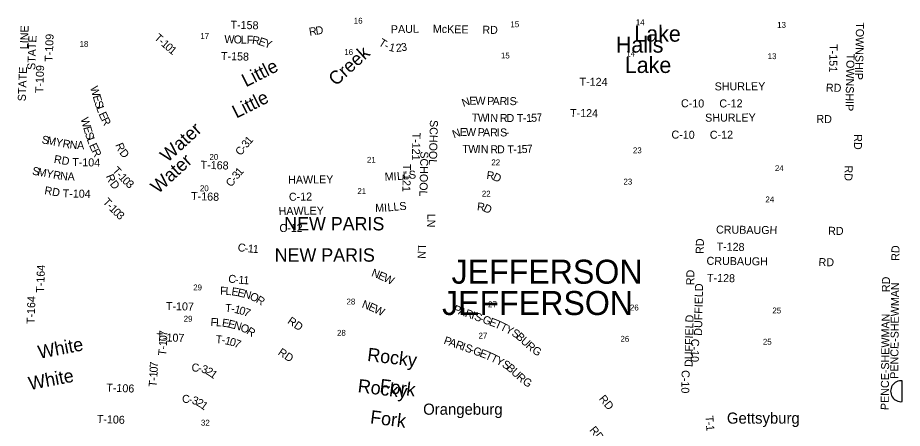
# Model space of a CAD drawing. Extents: x -21.9 to 47.3, y 14.1 to 48.7.
# Drawn here: x -21.92 to -15.64, y 44.7 to 47.62 of the extents above; entities that cross this region are included whole.
import ezdxf

# ---------------------------------------------------------------- set-up
doc = ezdxf.new("R2010")
doc.units = 0
for name, color, linetype in [('GM_X_Corporation_Text', 7, 'Continuous'), ('GM_X_County_Road_Text', 7, 'Continuous'), ('GM_X_Major_River_Text', 7, 'Continuous'), ('GM_X_Minor_Lake_Text', 7, 'Continuous'), ('GM_X_Minor_River_Text', 7, 'Continuous'), ('GM_X_Section_Text', 7, 'Continuous'), ('GM_X_Township_Road_Text', 7, 'Continuous'), ('GM_X_Township_Text', 7, 'Continuous'), ('GM_X_Unincorporated_Text', 7, 'Continuous')]:
    doc.layers.add(name, color=color, linetype=linetype)

msp = doc.modelspace()

# ---------------------------------------------------------------- linework, layer by layer
at = {"layer": 'GM_X_Major_River_Text'}
msp.add_line((-15.6413, 44.8898), (-15.6413, 45.0376), dxfattribs=at)
msp.add_arc((-15.6499, 44.9637), 0.0744, 83.38525, 276.61475, dxfattribs=at)

# ---------------------------------------------------------------- texts
at = {"layer": 'GM_X_Corporation_Text'}
for p in [(-20.0268, 46.1054), (-20.0942, 45.8832)]:
    msp.add_text('NEW PARIS', height=0.0947, rotation=0.00001, dxfattribs=at).set_placement(p)
at = {"layer": 'GM_X_County_Road_Text'}
for s, height, rotation, p in [('SHURLEY', 0.05682, 0.29863, (-16.9725, 47.0991)), ('RD', 0.05682, 359.01278, (-16.1837, 47.0907)), ('C-10', 0.05682, 359.31423, (-17.2119, 46.9797)), ('C-12', 0.05682, 0.3429, (-16.9393, 46.978)), ('SHURLEY', 0.05682, 0.29863, (-17.0399, 46.8769)), ('RD', 0.05682, 359.01278, (-16.2511, 46.8685)), ('1', 0.0568, 48.42145, (-20.27, 46.7132)), ('C-10', 0.05682, 359.31423, (-17.2793, 46.7575)), ('C-12', 0.05682, 0.3429, (-17.0067, 46.7558)), ('C', 0.0568, 51.88765, (-20.3347, 46.6316)), ('3', 0.0568, 50.98767, (-20.2916, 46.6865)), ('-', 0.0568, 51.69294, (-20.3059, 46.6683)), ('3', 0.0568, 50.98767, (-20.359, 46.4643)), ('1', 0.0568, 48.42145, (-20.3374, 46.491)), ('M', 0.0568, 1.38832, (-19.3133, 46.4591)), ('I', 0.0568, 3.49277, (-19.2494, 46.4606)), ('L', 0.0568, 5.02783, (-19.2244, 46.4622)), ('L', 0.0568, 5.39561, (-19.1817, 46.466)), ('S', 0.0568, 5.40075, (-19.1394, 46.47)), ('R', 0.0568, 353.33041, (-18.5934, 46.4706)), ('D', 0.0568, 334.82796, (-18.5517, 46.4665)), ('C', 0.0568, 51.88765, (-20.4021, 46.4094)), ('-', 0.0568, 51.69294, (-20.3733, 46.4461)), ('HAWLEY', 0.05682, 0.63509, (-19.9985, 46.4366)), ('C-12', 0.05682, 0.68708, (-19.9929, 46.3155)), ('HAWLEY', 0.05682, 0.63509, (-20.0659, 46.2144)), ('M', 0.0568, 1.38832, (-19.3807, 46.2369)), ('I', 0.0568, 3.49277, (-19.3168, 46.2385)), ('L', 0.0568, 5.02783, (-19.2918, 46.24)), ('L', 0.0568, 5.39561, (-19.2491, 46.2438)), ('S', 0.0568, 5.40075, (-19.2068, 46.2478)), ('R', 0.0568, 353.33041, (-18.6608, 46.2484)), ('D', 0.0568, 334.82796, (-18.6191, 46.2443)), ('C-12', 0.05682, 0.68708, (-20.0603, 46.0933)), ('C', 0.0568, 352.13029, (-20.3591, 45.9591)), ('1', 0.0568, 355.20707, (-20.2863, 45.9501)), ('RD', 0.05682, 89.01231, (-17.0506, 45.9379)), ('-', 0.0568, 354.33802, (-20.3105, 45.9525)), ('1', 0.0568, 355.53507, (-20.2511, 45.9471)), ('N', 0.0568, 339.45824, (-19.4123, 45.7825)), ('RD', 0.05682, 89.01231, (-17.118, 45.7157)), ('C', 0.0568, 352.13029, (-20.4265, 45.7369)), ('-', 0.0568, 354.33802, (-20.3779, 45.7303)), ('1', 0.0568, 355.20707, (-20.3537, 45.7279)), ('1', 0.0568, 355.53507, (-20.3185, 45.7249)), ('E', 0.0568, 335.24664, (-19.3665, 45.7653)), ('W', 0.0568, 334.78636, (-19.328, 45.7476)), ('DUFFIELD', 0.05682, 88.8627, (-17.0623, 45.3571)), ('N', 0.0568, 339.45824, (-19.4797, 45.5603)), ('E', 0.0568, 335.24664, (-19.4339, 45.5432)), ('W', 0.0568, 334.78636, (-19.3954, 45.5254)), ('P', 0.0568, 340.45593, (-18.8317, 45.5242)), ('A', 0.0568, 340.45494, (-18.7956, 45.5114)), ('R', 0.0568, 340.45674, (-18.7485, 45.4947)), ('I', 0.0568, 340.45204, (-18.7045, 45.4791)), ('S', 0.0568, 340.45729, (-18.6825, 45.4712)), ('DUFFIELD', 0.05682, 88.8627, (-17.1296, 45.135)), ('-', 0.0568, 340.45204, (-18.6464, 45.4584)), ('G', 0.0568, 340.41246, (-18.6244, 45.4506)), ('E', 0.0568, 339.43618, (-18.5775, 45.4339)), ('T', 0.0568, 335.95223, (-18.5386, 45.4194)), ('T', 0.0568, 333.94644, (-18.5003, 45.4023)), ('Y', 0.0568, 333.69541, (-18.4621, 45.3836)), ('S', 0.0568, 329.73826, (-18.4182, 45.362)), ('B', 0.0568, 318.00507, (-18.3876, 45.3445)), ('P', 0.0568, 340.45593, (-18.8991, 45.302)), ('A', 0.0568, 340.45494, (-18.863, 45.2892)), ('R', 0.0568, 340.45674, (-18.8159, 45.2725)), ('U', 0.0568, 317.05527, (-18.3531, 45.3134)), ('R', 0.0568, 317.31826, (-18.3163, 45.2791)), ('C-10', 0.05682, 268.97107, (-17.1394, 45.336)), ('I', 0.0568, 340.45204, (-18.7719, 45.2569)), ('S', 0.0568, 340.45729, (-18.7499, 45.2491)), ('-', 0.0568, 340.45204, (-18.7138, 45.2362)), ('G', 0.0568, 340.41246, (-18.6918, 45.2284)), ('E', 0.0568, 339.43618, (-18.6449, 45.2118)), ('G', 0.0568, 328.02168, (-18.2728, 45.2405)), ('T', 0.0568, 335.95223, (-18.606, 45.1972)), ('T', 0.0568, 333.94644, (-18.5677, 45.1801)), ('Y', 0.0568, 333.69541, (-18.5295, 45.1614)), ('C', 0.0568, 357.95416, (-20.6846, 45.1039)), ('-', 0.0568, 352.33407, (-20.6395, 45.1023)), ('3', 0.0568, 341.09389, (-20.6192, 45.0999)), ('2', 0.0568, 329.85372, (-20.5888, 45.0898)), ('S', 0.0568, 329.73826, (-18.4856, 45.1398)), ('B', 0.0568, 318.00507, (-18.455, 45.1223)), ('U', 0.0568, 317.05527, (-18.4205, 45.0912)), ('1', 0.0568, 324.23363, (-20.5597, 45.073)), ('R', 0.0568, 317.31826, (-18.3837, 45.057)), ('C-10', 0.05682, 268.97107, (-17.2068, 45.1138)), ('G', 0.0568, 328.02168, (-18.3402, 45.0183)), ('C', 0.0568, 357.95416, (-20.752, 44.8817)), ('RD', 0.05682, 309.74193, (-17.7969, 44.9085)), ('-', 0.0568, 352.33407, (-20.7069, 44.8801)), ('3', 0.0568, 341.09389, (-20.6866, 44.8777)), ('2', 0.0568, 329.85372, (-20.6562, 44.8676)), ('1', 0.0568, 324.23363, (-20.6271, 44.8508)), ('RD', 0.05682, 309.74193, (-17.8643, 44.6863))]:
    msp.add_text(s, height=height, rotation=rotation, dxfattribs=at).set_placement(p)
at = {"layer": 'GM_X_Minor_Lake_Text'}
for s, rotation, p in [('Lake', 0.00663, (-17.5424, 47.4451)), ('Halls', 0.00679, (-17.6738, 47.3673)), ('Lake', 0.00663, (-17.6098, 47.2229))]:
    msp.add_text(s, height=0.11363, rotation=rotation, dxfattribs=at).set_placement(p)
at = {"layer": 'GM_X_Minor_River_Text'}
for s, height, rotation, p in [('Creek', 0.09467, 42.35798, (-19.6597, 47.1263)), ('Little', 0.09468, 26.87284, (-20.2983, 47.1205)), ('Little', 0.09468, 26.87284, (-20.3657, 46.8983)), ('Water', 0.09466, 42.35347, (-20.854, 46.5836)), ('Water', 0.09466, 42.35347, (-20.9214, 46.3614)), ('White', 0.09469, 10.82648, (-21.764, 45.1933)), ('Rocky', 0.09469, 352.89105, (-19.4408, 45.1793)), ('White', 0.09469, 10.82648, (-21.8314, 44.9711)), ('Rocky', 0.09469, 352.89105, (-19.5082, 44.9571)), ('Fork', 0.09469, 352.89084, (-19.3528, 44.9581)), ('Fork', 0.09469, 352.89084, (-19.4202, 44.7359))]:
    msp.add_text(s, height=height, rotation=rotation, dxfattribs=at).set_placement(p)
at = {"layer": 'GM_X_Section_Text'}
for s, p in [('16', (-19.5328, 47.573)), ('15', (-18.4216, 47.5481)), ('14', (-17.532, 47.5621)), ('13', (-16.5291, 47.5434)), ('18', (-21.4785, 47.4079)), ('17', (-20.6215, 47.4651)), ('16', (-19.6002, 47.3508)), ('15', (-18.489, 47.3259)), ('14', (-17.5994, 47.3399)), ('13', (-16.5965, 47.3212)), ('23', (-17.5524, 46.653)), ('20', (-20.557, 46.6059)), ('21', (-19.4399, 46.5854)), ('22', (-18.557, 46.5671)), ('24', (-16.5453, 46.5262)), ('23', (-17.6198, 46.4308)), ('20', (-20.6244, 46.3837)), ('21', (-19.5073, 46.3632)), ('22', (-18.6244, 46.3449)), ('24', (-16.6127, 46.3041)), ('29', (-20.6724, 45.6793)), ('28', (-19.5845, 45.5793)), ('27', (-18.5803, 45.5593)), ('26', (-17.5737, 45.5368)), ('25', (-16.5632, 45.5159)), ('29', (-20.7398, 45.4571)), ('28', (-19.6519, 45.3571)), ('27', (-18.6477, 45.3371)), ('26', (-17.641, 45.3146)), ('25', (-16.6306, 45.2937)), ('32', (-20.617, 44.7193))]:
    msp.add_text(s, height=0.04186, rotation=0.00001, dxfattribs=at).set_placement(p)
at = {"layer": 'GM_X_Township_Road_Text'}
for s, height, rotation, p in [('T-158', 0.05682, 358.59567, (-20.4081, 47.5373)), ('TOWNSHIP', 0.05682, 268.80363, (-15.9692, 47.5837)), ('LINE', 0.05682, 87.9954, (-21.8454, 47.391)), ('R', 0.0568, 9.17599, (-19.8459, 47.4866)), ('D', 0.0568, 8.20602, (-19.8, 47.494)), ('PAUL', 0.05682, 1.32402, (-19.2693, 47.5044)), ('McKEE', 0.05682, 358.78533, (-18.9726, 47.5085)), ('RD', 0.05682, 359.02012, (-18.6213, 47.5019)), ('STATE', 0.05682, 87.78889, (-21.7931, 47.2434)), ('T-109', 0.05682, 87.7543, (-21.6697, 47.3012)), ('T', 0.0568, 318.26325, (-20.9533, 47.4662)), ('-', 0.0568, 318.28073, (-20.9215, 47.4379)), ('1', 0.0568, 318.34053, (-20.9041, 47.4223)), ('W', 0.0568, 358.48093, (-20.4517, 47.4352)), ('O', 0.0568, 358.48079, (-20.3859, 47.4334)), ('L', 0.0568, 358.48423, (-20.3359, 47.4321)), ('F', 0.0568, 358.3843, (-20.2934, 47.431)), ('R', 0.0568, 352.50053, (-20.2567, 47.43)), ('E', 0.0568, 341.17068, (-20.2133, 47.4246)), ('Y', 0.0568, 340.99138, (-20.1731, 47.4109)), ('T', 0.0568, 328.11455, (-19.3613, 47.4234)), ('0', 0.0568, 318.59425, (-20.8777, 47.3989)), ('1', 0.0568, 320.1977, (-20.8502, 47.3746)), ('-', 0.0568, 330.34481, (-19.3231, 47.3998)), ('1', 0.0568, 345.41201, (-19.2878, 47.3821)), ('2', 0.0568, 6.3204, (-19.2315, 47.3717)), ('3', 0.0568, 10.08346, (-19.1927, 47.3761)), ('T-151', 0.05682, 268.87678, (-16.1567, 47.4281)), ('T-158', 0.05682, 358.59567, (-20.4755, 47.3151)), ('TOWNSHIP', 0.05682, 268.80363, (-16.0366, 47.3615)), ('STATE', 0.05682, 87.78889, (-21.8605, 47.0212)), ('T-109', 0.05682, 87.7543, (-21.7371, 47.079)), ('W', 0.0568, 286.14534, (-21.4043, 47.1205)), ('T-124', 0.05682, 359.71822, (-17.9312, 47.1323)), ('E', 0.0568, 286.28182, (-21.3859, 47.0571)), ('S', 0.0568, 287.55111, (-21.3736, 47.015)), ('N', 0.0568, 19.33248, (-18.755, 46.981)), ('E', 0.0568, 1.79168, (-18.7123, 46.9967)), ('W', 0.0568, 359.31385, (-18.6705, 46.998)), ('P', 0.0568, 359.04386, (-18.5872, 46.9969)), ('A', 0.0568, 359.04555, (-18.5489, 46.9963)), ('R', 0.0568, 359.09318, (-18.4988, 46.9954)), ('I', 0.0568, 359.59008, (-18.4516, 46.9947)), ('S', 0.0568, 0.40975, (-18.4274, 46.9945)), ('-', 0.0568, 1.18896, (-18.3882, 46.9948)), ('L', 0.0568, 289.94001, (-21.3612, 46.976)), ('E', 0.0568, 294.21387, (-21.345, 46.9318)), ('T-124', 0.05682, 359.71822, (-17.9986, 46.9101)), ('W', 0.0568, 286.14534, (-21.4717, 46.8983)), ('R', 0.0568, 295.97741, (-21.3267, 46.8913)), ('SCHOOL', 0.05682, 268.62372, (-18.9925, 46.8895)), ('T', 0.0568, 359.14285, (-18.6964, 46.8782)), ('W', 0.0568, 359.1423, (-18.6539, 46.8776)), ('I', 0.0568, 359.14869, (-18.588, 46.8766)), ('N', 0.0568, 359.14875, (-18.5647, 46.8762)), ('R', 0.0568, 359.28834, (-18.4971, 46.8752)), ('D', 0.0568, 0.01456, (-18.4496, 46.8747)), ('T', 0.0568, 1.08432, (-18.3755, 46.8739)), ('-', 0.0568, 1.12693, (-18.333, 46.8747)), ('1', 0.0568, 1.27135, (-18.3095, 46.8752)), ('5', 0.0568, 1.79762, (-18.274, 46.876)), ('7', 0.0568, 5.18162, (-18.2353, 46.8773)), ('E', 0.0568, 286.28182, (-21.4533, 46.8349)), ('N', 0.0568, 19.33248, (-18.8224, 46.7588)), ('E', 0.0568, 1.79168, (-18.7797, 46.7745)), ('W', 0.0568, 359.31385, (-18.7378, 46.7758)), ('P', 0.0568, 359.04386, (-18.6546, 46.7747)), ('A', 0.0568, 359.04555, (-18.6163, 46.7741)), ('R', 0.0568, 359.09318, (-18.5662, 46.7733)), ('I', 0.0568, 359.59008, (-18.519, 46.7725)), ('S', 0.0568, 0.40975, (-18.4948, 46.7723)), ('S', 0.0568, 349.34784, (-21.7501, 46.7244)), ('M', 0.0568, 349.34924, (-21.7124, 46.7173)), ('Y', 0.0568, 349.34926, (-21.6518, 46.7059)), ('S', 0.0568, 287.55111, (-21.441, 46.7928)), ('L', 0.0568, 289.94001, (-21.4286, 46.7538)), ('T-121', 0.05682, 268.59595, (-19.116, 46.8)), ('-', 0.0568, 1.18896, (-18.4556, 46.7726)), ('RD', 0.05682, 269.50588, (-15.9834, 46.7882)), ('R', 0.0568, 349.95064, (-21.6021, 46.6965)), ('N', 0.0568, 354.61352, (-21.5511, 46.6877)), ('A', 0.0568, 358.73308, (-21.4969, 46.6828)), ('E', 0.0568, 294.21387, (-21.4124, 46.7096)), ('R', 0.0568, 292.28528, (-21.2257, 46.7131)), ('T', 0.0568, 359.14285, (-18.7637, 46.656)), ('W', 0.0568, 359.1423, (-18.7213, 46.6554)), ('I', 0.0568, 359.14869, (-18.6554, 46.6544)), ('N', 0.0568, 359.14875, (-18.6321, 46.6541)), ('R', 0.0568, 359.28834, (-18.5645, 46.6531)), ('D', 0.0568, 0.01456, (-18.517, 46.6525)), ('T', 0.0568, 1.08432, (-18.4429, 46.6517)), ('1', 0.0568, 1.27135, (-18.3769, 46.653)), ('5', 0.0568, 1.79762, (-18.3413, 46.6538)), ('7', 0.0568, 5.18162, (-18.3027, 46.6551)), ('RD', 0.05682, 350.04916, (-21.6634, 46.5855)), ('R', 0.0568, 295.97741, (-21.3941, 46.6691)), ('D', 0.0568, 308.63938, (-21.1992, 46.655)), ('SCHOOL', 0.05682, 268.62372, (-19.0599, 46.6673)), ('-', 0.0568, 1.12693, (-18.4004, 46.6526)), ('T-104', 0.05682, 358.88104, (-21.5312, 46.5623)), ('T-168', 0.05682, 358.30687, (-20.6203, 46.5431)), ('T-121', 0.05682, 268.59595, (-19.1834, 46.5778)), ('S', 0.0568, 349.34784, (-21.8175, 46.5022)), ('M', 0.0568, 349.34924, (-21.7798, 46.4951)), ('Y', 0.0568, 349.34926, (-21.7192, 46.4837)), ('R', 0.0568, 349.95064, (-21.6694, 46.4743)), ('N', 0.0568, 354.61352, (-21.6185, 46.4655)), ('A', 0.0568, 358.73308, (-21.5643, 46.4606)), ('R', 0.0568, 292.28528, (-21.2931, 46.4909)), ('T', 0.0568, 313.0373, (-21.2502, 46.5261)), ('-', 0.0568, 313.12882, (-21.2212, 46.4949)), ('RD', 0.05682, 269.50588, (-16.0508, 46.566)), ('D', 0.0568, 308.63938, (-21.2666, 46.4328)), ('1', 0.0568, 313.48218, (-21.2049, 46.4776)), ('0', 0.0568, 314.85589, (-21.1798, 46.4511)), ('3', 0.0568, 319.26324, (-21.1543, 46.4256)), ('RD', 0.05682, 350.04916, (-21.7308, 46.3633)), ('T-104', 0.05682, 358.88104, (-21.5986, 46.3401)), ('T', 0.0568, 313.0373, (-21.3176, 46.3039)), ('T-168', 0.05682, 358.30687, (-20.6877, 46.3209)), ('-', 0.0568, 313.12882, (-21.2885, 46.2727)), ('1', 0.0568, 313.48218, (-21.2723, 46.2554)), ('0', 0.0568, 314.85589, (-21.2472, 46.229)), ('3', 0.0568, 319.26324, (-21.2217, 46.2034)), ('LN', 0.05682, 268.4517, (-19.0101, 46.2244)), ('CRUBAUGH', 0.05682, 359.38823, (-16.963, 46.0832)), ('RD', 0.05682, 359.50635, (-16.168, 46.0741)), ('T-128', 0.05682, 359.15794, (-16.9597, 45.9623)), ('LN', 0.05682, 268.4517, (-19.0775, 46.0022)), ('RD', 0.05682, 89.50633, (-15.6622, 45.8894)), ('CRUBAUGH', 0.05682, 359.38823, (-17.0304, 45.8611)), ('RD', 0.05682, 359.50635, (-16.2354, 45.8519)), ('T-164', 0.05682, 88.03472, (-21.7305, 45.6617)), ('T-128', 0.05682, 359.15794, (-17.0271, 45.7401)), ('RD', 0.05682, 89.50633, (-15.7296, 45.6672)), ('F', 0.0568, 357.68067, (-20.4825, 45.649)), ('L', 0.0568, 356.96007, (-20.4444, 45.6475)), ('E', 0.0568, 352.17589, (-20.4032, 45.6454)), ('E', 0.0568, 346.26194, (-20.3626, 45.6399)), ('PENCE-SHEWMAN', 0.056818, 89.44451, (-15.6706, 45.0519)), ('T-164', 0.05682, 88.03472, (-21.7979, 45.4395)), ('N', 0.0568, 344.29691, (-20.3218, 45.6299)), ('O', 0.0568, 336.52333, (-20.2756, 45.6171)), ('R', 0.0568, 327.66401, (-20.2318, 45.5982)), ('T-107', 0.05682, 358.60252, (-20.8665, 45.5406)), ('T', 0.0568, 355.85648, (-20.4472, 45.5274)), ('1', 0.0568, 346.00841, (-20.3843, 45.521)), ('0', 0.0568, 344.52854, (-20.3507, 45.5127)), ('-', 0.0568, 350.85161, (-20.4061, 45.5245)), ('7', 0.0568, 338.38897, (-20.3185, 45.5038)), ('PENCE-SHEWMAN', 0.056818, 89.44451, (-15.738, 44.8297)), ('F', 0.0568, 357.68067, (-20.5499, 45.4269)), ('L', 0.0568, 356.96007, (-20.5117, 45.4253)), ('E', 0.0568, 352.17589, (-20.4706, 45.4232)), ('E', 0.0568, 346.26194, (-20.43, 45.4177)), ('N', 0.0568, 344.29691, (-20.3892, 45.4077)), ('O', 0.0568, 336.52333, (-20.343, 45.3949)), ('RD', 0.05682, 326.17288, (-20.0083, 45.4494)), ('7', 0.0568, 87.82595, (-20.8564, 45.3529)), ('R', 0.0568, 327.66401, (-20.2992, 45.376)), ('T-107', 0.05682, 358.60252, (-20.9339, 45.3184)), ('1', 0.0568, 87.50514, (-20.8593, 45.2826)), ('0', 0.0568, 87.76111, (-20.8578, 45.3179)), ('T', 0.0568, 355.85648, (-20.5145, 45.3052)), ('-', 0.0568, 350.85161, (-20.4735, 45.3023)), ('1', 0.0568, 346.00841, (-20.4517, 45.2989)), ('0', 0.0568, 344.52854, (-20.4181, 45.2905)), ('7', 0.0568, 338.38897, (-20.3859, 45.2817)), ('T', 0.0568, 83.51685, (-20.8657, 45.2128)), ('-', 0.0568, 86.96836, (-20.8606, 45.2587)), ('RD', 0.05682, 326.17288, (-20.0757, 45.2272)), ('0', 0.0568, 87.76111, (-20.9251, 45.0957)), ('7', 0.0568, 87.82595, (-20.9238, 45.1307)), ('1', 0.0568, 87.50514, (-20.9267, 45.0604)), ('T-106', 0.05682, 357.75442, (-21.2896, 44.9615)), ('T', 0.0568, 83.51685, (-20.9331, 44.9906)), ('-', 0.0568, 86.96836, (-20.9279, 45.0365)), ('T-106', 0.05682, 357.75442, (-21.357, 44.7393)), ('T', 0.0568, 274.3476, (-17.0391, 44.7876)), ('1', 0.0568, 274.89319, (-17.034, 44.7213)), ('-', 0.0568, 274.45309, (-17.0358, 44.7451))]:
    msp.add_text(s, height=height, rotation=rotation, dxfattribs=at).set_placement(p)
at = {"layer": 'GM_X_Township_Text'}
for p in [(-18.8394, 45.7268), (-18.9068, 45.5046)]:
    msp.add_text('JEFFERSON', height=0.17045, rotation=0.00001, dxfattribs=at).set_placement(p)
at = {"layer": 'GM_X_Unincorporated_Text'}
for s, p in [('Orangeburg', (-19.0407, 44.7967)), ('Gettsyburg', (-16.8857, 44.7333))]:
    msp.add_text(s, height=0.07898, rotation=0.00001, dxfattribs=at).set_placement(p)

doc.saveas('drawing.dxf')
